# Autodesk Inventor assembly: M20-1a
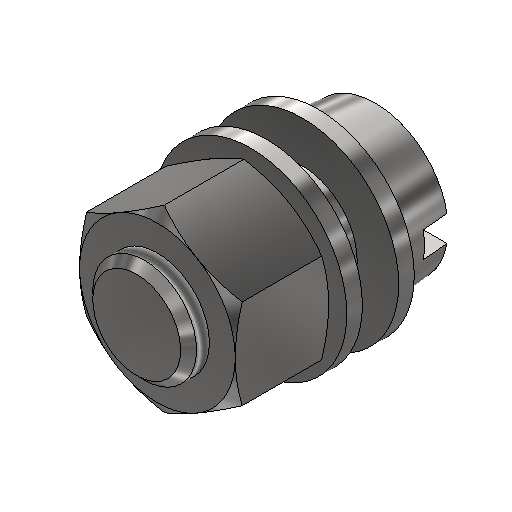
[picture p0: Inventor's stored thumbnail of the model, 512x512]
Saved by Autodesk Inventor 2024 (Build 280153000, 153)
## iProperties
Company: ATC
ClientObjectVersion: 1
Created: 2023-03
Part Number: M20-1a
Document SubType Name: Assembly
Designer: Andrzej Jaskulski
Checked By: A.J.
Engr Approved By: Andrzej Jaskulski
Mfg Approved By: Andrzej Jaskulski
Authority: A.J.
Author: Andrzej Jaskulski
Title: A.J.: Kurs R2024-MEP
Revision Number: 1/24
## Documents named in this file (4)
- C:\Users\AndJas\Documents\R2024-MEP\Obszar roboczy\SPEC\GOTOWE\SPEC-GOTOWE\Design Accelerator\M20-1a.iam
- C:\Users\AndJas\Documents\R2024-MEP\Obszar roboczy\SPEC\GOTOWE\SPEC-GOTOWE\PN\PN-78_M-82005 - 21.ipt
- C:\Users\AndJas\Documents\R2024-MEP\Obszar roboczy\SPEC\GOTOWE\SPEC-GOTOWE\PN\PN-85_M-82215 - M 20 x 35 - 2,5.ipt
- C:\Users\AndJas\Documents\R2024-MEP\Obszar roboczy\SPEC\GOTOWE\SPEC-GOTOWE\PN\PN-86_M-82144 - M20.ipt
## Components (4 placed, 3 different names)
1. PN-78/M-82005 21:1
2. PN-85/M-82215 M 20 x 35:1
3. PN-78/M-82005 21:2
4. PN-86/M-82144 M20:1
